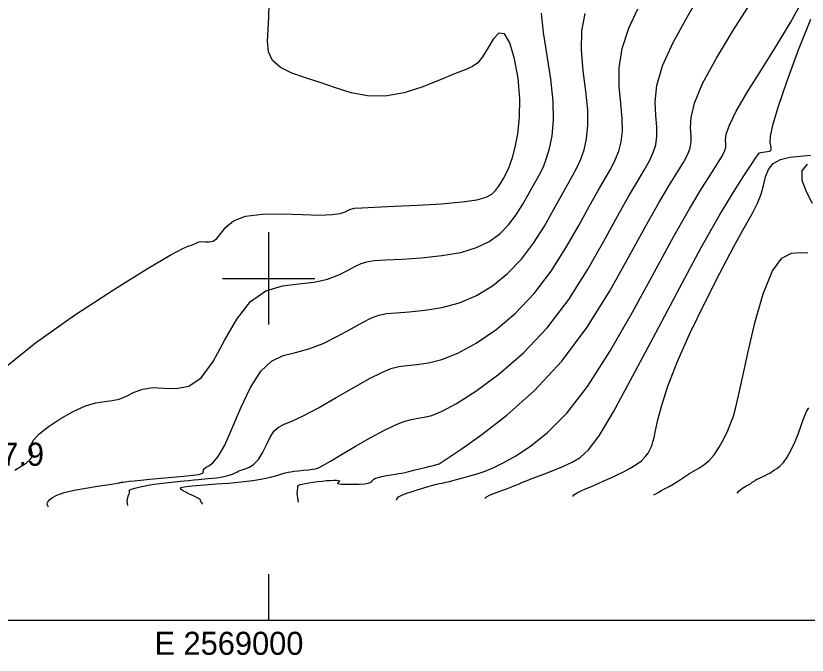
# Model space of a CAD drawing. Extents: x 2566142 to 2571431, y 418755 to 421584.
# Drawn here: x 2568835 to 2569351, y 418755 to 419171 of the extents above; entities that cross this region are included whole.
import ezdxf

# ---------------------------------------------------------------- set-up
doc = ezdxf.new("R2010")
doc.units = 0
for name, color, linetype in [('Contour_ADS_Major', 7, 'Continuous'), ('Contour_ADS_Minor', 7, 'Continuous'), ('Contour_ADS_Spot_Elevation', 7, 'Continuous'), ('Contour_ADS_State_Plane_Border', 7, 'Continuous'), ('Contour_ADS_Tick', 7, 'Continuous')]:
    doc.layers.add(name, color=color, linetype=linetype)

# ---------------------------------------------------------------- blocks, each defined once
blk = doc.blocks.new('S890')
at = {"layer": 'Contour_ADS_Tick'}
for p, q in [((0, -0.5), (0, 0.5)), ((-0.5, 0), (0.5, 0))]:
    blk.add_line(p, q, dxfattribs=at)

msp = doc.modelspace()

# ---------------------------------------------------------------- linework, layer by layer
at = {"layer": 'Contour_ADS_Major'}
for points in [[(2568856.63, 418851.15), (2568856.2, 418851.99), (2568855.76, 418852.87), (2568855.59, 418853.25), (2568855.55, 418853.49), (2568855.64, 418853.76), (2568855.92, 418854.2), (2568856.47, 418854.92), (2568857.4, 418856.02), (2568859.11, 418857.42), (2568862.07, 418858.99), (2568866.75, 418860.6), (2568873.34, 418862.14), (2568880.97, 418863.54), (2568888.49, 418864.74), (2568894.78, 418865.68), (2568898.97, 418866.32), (2568901.36, 418866.72), (2568902.55, 418866.95), (2568903.11, 418867.09), (2568903.56, 418867.2), (2568904.19, 418867.33), (2568905.17, 418867.48), (2568906.73, 418867.67), (2568909.05, 418867.94), (2568912.33, 418868.29), (2568916.78, 418868.72), (2568922.57, 418869.26), (2568929.71, 418869.9), (2568937.42, 418870.59), (2568944.72, 418871.28), (2568950.63, 418871.91), (2568954.44, 418872.45), (2568956.46, 418872.93), (2568957.26, 418873.43), (2568957.41, 418874), (2568957.43, 418874.69), (2568957.59, 418875.46), (2568958.11, 418876.27), (2568959.21, 418877.06), (2568961.06, 418877.97), (2568963.7, 418879.91), (2568967.13, 418884.01), (2568971.34, 418891.37), (2568976.3, 418902.55), (2568981.94, 418915.83), (2568988.14, 418928.95), (2568994.79, 418939.61), (2569001.83, 418946.22), (2569009.32, 418949.73), (2569017.36, 418951.8), (2569026.07, 418954.05), (2569035.42, 418957.71), (2569044.84, 418962.37), (2569053.64, 418967.2), (2569061.12, 418971.37), (2569066.89, 418974.27), (2569071.74, 418976.05), (2569076.79, 418977.08), (2569083.13, 418977.69), (2569091.56, 418978.28), (2569101.68, 418979.26), (2569112.8, 418981.08), (2569124.2, 418984.17), (2569135.29, 418988.9), (2569145.82, 418995.25), (2569155.64, 419003.14), (2569164.61, 419012.48), (2569172.59, 419023.03), (2569179.6, 419034.04), (2569185.62, 419044.63), (2569190.68, 419053.9), (2569194.82, 419061.25), (2569198.2, 419067.15), (2569201, 419072.36), (2569203.4, 419077.64), (2569205.51, 419083.68), (2569207.13, 419090.84), (2569207.99, 419099.41), (2569207.81, 419109.71), (2569206.53, 419121.83), (2569204.84, 419135.05), (2569203.67, 419148.48), (2569203.93, 419161.21), (2569206.14, 419172.49)], [(2569140.86, 418856.83), (2569141.86, 418857.77), (2569144.28, 418859.07), (2569147.13, 418860.21), (2569150.12, 418861.26), (2569152.97, 418862.28), (2569155.56, 418863.26), (2569157.82, 418864.15), (2569159.66, 418864.89), (2569161.04, 418865.45), (2569162.12, 418865.9), (2569163.07, 418866.3), (2569164.08, 418866.73), (2569165.37, 418867.27), (2569167.22, 418868.03), (2569169.95, 418869.11), (2569173.88, 418870.63), (2569179.16, 418872.65), (2569185.32, 418875.06), (2569191.71, 418877.68), (2569197.71, 418880.37), (2569202.97, 418883.33), (2569208.4, 418888.36), (2569215.21, 418897.61), (2569224.6, 418913.26), (2569237.32, 418936.48), (2569252.19, 418964.51), (2569267.56, 418993.61), (2569281.79, 419020.02), (2569293.53, 419040.78), (2569302.71, 419056.04), (2569309.56, 419066.75), (2569314.29, 419073.85), (2569317.21, 419078.24), (2569318.85, 419080.63), (2569319.81, 419081.65), (2569320.68, 419081.98), (2569321.93, 419082.15), (2569323.44, 419082.32), (2569324.95, 419082.55), (2569326.22, 419082.87), (2569327.03, 419083.33), (2569327.4, 419084.03), (2569327.42, 419085.03), (2569327.16, 419086.42), (2569326.79, 419088.49), (2569326.96, 419092.43), (2569328.4, 419099.63), (2569331.85, 419111.48), (2569337.75, 419128.64), (2569345.24, 419148.77), (2569353.19, 419168.77)]]:
    msp.add_lwpolyline(points, dxfattribs=at)
at = {"layer": 'Contour_ADS_Minor'}
for points in [[(2568957.05, 418853.16), (2568956.47, 418853.88), (2568955.83, 418854.8), (2568955.64, 418855.23), (2568955.6, 418855.5), (2568955.61, 418855.71), (2568955.61, 418855.87), (2568955.56, 418856.01), (2568955.4, 418856.15), (2568955.04, 418856.35), (2568954.38, 418856.68), (2568953.32, 418857.2), (2568951.81, 418857.96), (2568949.97, 418858.88), (2568947.99, 418859.89), (2568946.03, 418860.88), (2568944.29, 418861.78), (2568943.03, 418862.58), (2568942.53, 418863.28), (2568943.05, 418863.88), (2568944.84, 418864.4), (2568947.99, 418864.86), (2568952.51, 418865.3), (2568958.47, 418865.74), (2568965.78, 418866.22), (2568973.86, 418866.79), (2568982.04, 418867.5), (2568989.61, 418868.38), (2568996.02, 418869.46), (2569001.25, 418870.64), (2569005.38, 418871.77), (2569008.51, 418872.72), (2569010.8, 418873.39), (2569012.62, 418873.83), (2569014.4, 418874.15), (2569016.58, 418874.44), (2569019.43, 418874.78), (2569022.66, 418875.14), (2569025.83, 418875.48), (2569028.5, 418875.76), (2569030.47, 418876.03), (2569032.44, 418876.68), (2569035.37, 418878.18), (2569040.2, 418881), (2569047.53, 418885.41), (2569056.54, 418890.78), (2569066.06, 418896.29), (2569074.92, 418901.1), (2569082.22, 418904.56), (2569088.11, 418906.81), (2569092.97, 418908.17), (2569097.24, 418908.96), (2569101.39, 418909.6), (2569106.32, 418910.85), (2569112.98, 418913.57), (2569122.35, 418918.61), (2569135.01, 418926.65), (2569149.99, 418937.67), (2569165.93, 418951.45), (2569181.47, 418967.81), (2569195.48, 418986.31), (2569207.75, 419005.62), (2569218.31, 419024.18), (2569227.19, 419040.44), (2569234.43, 419053.24), (2569240.2, 419062.97), (2569244.68, 419070.46), (2569248.07, 419076.5), (2569250.53, 419081.84), (2569252.11, 419087), (2569252.85, 419092.44), (2569252.78, 419098.63), (2569252.1, 419105.99), (2569251.75, 419114.85), (2569252.83, 419125.5), (2569256.44, 419138.25), (2569263.19, 419153.05), (2569271.7, 419168.54), (2569280.09, 419183.01)], [(2568827.81, 418941.71), (2568848.18, 418958.1), (2568873.59, 418975.99), (2568899.5, 418992.96), (2568921.42, 419006.59), (2568935.92, 419015.13), (2568944.04, 419019.47), (2568947.92, 419021.12), (2568949.7, 419021.64), (2568951.15, 419022.26), (2568952.72, 419023.02), (2568954.46, 419023.69), (2568956.45, 419024.01), (2568958.73, 419023.88), (2568961.22, 419023.76), (2568963.77, 419024.26), (2568966.28, 419025.97), (2568968.79, 419029.23), (2568972.1, 419033.37), (2568977.17, 419037.43), (2568984.97, 419040.48), (2568996.02, 419041.85), (2569008.95, 419041.96), (2569021.94, 419041.5), (2569033.19, 419041.17), (2569041.29, 419041.49), (2569046.59, 419042.34), (2569049.86, 419043.43), (2569051.86, 419044.44), (2569053.47, 419045.16), (2569055.95, 419045.65), (2569060.67, 419046.03), (2569069.02, 419046.43), (2569081.72, 419046.96), (2569097.04, 419047.67), (2569112.61, 419048.58), (2569126.05, 419049.73), (2569135.56, 419051.14), (2569141.64, 419052.84), (2569145.35, 419054.83), (2569147.74, 419057.14), (2569149.71, 419059.74), (2569151.44, 419062.46), (2569152.93, 419065.07), (2569154.18, 419067.36), (2569155.22, 419069.26), (2569156.21, 419071.33), (2569157.32, 419074.27), (2569158.73, 419078.79), (2569160.5, 419085.46), (2569162.25, 419094.19), (2569163.49, 419104.76), (2569163.7, 419116.95), (2569162.54, 419130.24), (2569160.23, 419143), (2569157.11, 419153.29), (2569153.55, 419159.21), (2569149.86, 419159.5), (2569146.19, 419155.65), (2569142.65, 419149.82), (2569139.36, 419144.18), (2569136.26, 419140.36), (2569132.72, 419137.9), (2569127.93, 419135.82), (2569121.1, 419133.14), (2569111.7, 419129.2), (2569100.4, 419124.76), (2569088.15, 419120.87), (2569075.9, 419118.62), (2569064.4, 419118.77), (2569053.65, 419120.83), (2569043.43, 419123.98), (2569033.54, 419127.42), (2569023.93, 419130.56), (2569015.11, 419133.66), (2569007.77, 419137.22), (2569002.58, 419141.72), (2568999.96, 419147.49), (2568999.27, 419154.35), (2568999.64, 419161.94), (2569000.19, 419169.92), (2569000.36, 419178.04)], [(2568908.25, 418852.18), (2568907.88, 418854.99), (2568908.16, 418857.32), (2568908.74, 418858.98), (2568909.23, 418860.13), (2568909.34, 418860.93), (2568909.23, 418861.48), (2568909.16, 418861.88), (2568909.4, 418862.23), (2568910.14, 418862.62), (2568911.32, 418863.04), (2568912.8, 418863.49), (2568914.48, 418863.94), (2568916.28, 418864.4), (2568918.49, 418864.88), (2568921.43, 418865.41), (2568925.47, 418866), (2568930.75, 418866.66), (2568936.72, 418867.35), (2568942.62, 418868), (2568947.73, 418868.55), (2568951.48, 418868.94), (2568954.18, 418869.22), (2568956.3, 418869.41), (2568958.33, 418869.56), (2568960.67, 418869.72), (2568963.29, 418869.93), (2568966.08, 418870.23), (2568968.91, 418870.67), (2568971.67, 418871.26), (2568974.21, 418871.95), (2568976.41, 418872.68), (2568978.12, 418873.36), (2568979.3, 418873.95), (2568980.22, 418874.46), (2568981.22, 418874.96), (2568982.65, 418875.47), (2568984.77, 418876.11), (2568987.42, 418877.18), (2568990.34, 418879.05), (2568993.26, 418882.11), (2568995.98, 418886.51), (2568998.55, 418891.63), (2569001.06, 418896.63), (2569003.6, 418900.68), (2569006.38, 418903.25), (2569009.99, 418905.06), (2569015.14, 418907.13), (2569022.52, 418910.49), (2569032.49, 418915.82), (2569043.97, 418922.38), (2569055.53, 418929.08), (2569065.75, 418934.84), (2569073.6, 418938.83), (2569079.64, 418941.26), (2569084.85, 418942.6), (2569090.18, 418943.33), (2569096.48, 418943.94), (2569104, 418945.05), (2569112.89, 418947.32), (2569123.28, 418951.39), (2569135.15, 418957.77), (2569147.9, 418966.46), (2569160.78, 418977.3), (2569173.04, 418990.14), (2569184.04, 419004.67), (2569193.67, 419019.83), (2569201.97, 419034.41), (2569208.94, 419047.17), (2569214.63, 419057.24), (2569219.2, 419065.06), (2569222.84, 419071.41), (2569225.73, 419077.07), (2569228.02, 419082.76), (2569229.62, 419088.92), (2569230.42, 419095.93), (2569230.29, 419104.17), (2569229.31, 419113.91), (2569228.3, 419124.95), (2569228.25, 419136.99), (2569230.18, 419149.73), (2569234.66, 419162.77), (2569240.51, 419175.34)], [(2569019.46, 418854.41), (2569018.88, 418857.14), (2569018.63, 418860.09), (2569018.71, 418862.2), (2569018.9, 418863.63), (2569019.02, 418864.56), (2569019.2, 418865.12), (2569019.63, 418865.48), (2569020.48, 418865.77), (2569021.9, 418866.11), (2569023.84, 418866.5), (2569026.21, 418866.92), (2569028.92, 418867.34), (2569031.86, 418867.74), (2569034.87, 418868.08), (2569037.76, 418868.36), (2569040.36, 418868.55), (2569042.51, 418868.64), (2569044.17, 418868.62), (2569045.35, 418868.52), (2569046.04, 418868.33), (2569046.26, 418868.08), (2569046.12, 418867.78), (2569045.75, 418867.45), (2569045.27, 418867.12), (2569044.87, 418866.81), (2569044.86, 418866.53), (2569045.62, 418866.3), (2569047.51, 418866.14), (2569050.72, 418866.06), (2569054.74, 418866.07), (2569058.85, 418866.18), (2569062.37, 418866.4), (2569064.75, 418866.73), (2569066.15, 418867.15), (2569066.91, 418867.64), (2569067.35, 418868.17), (2569067.79, 418868.73), (2569068.44, 418869.3), (2569069.53, 418869.89), (2569071.27, 418870.48), (2569073.77, 418871.07), (2569076.74, 418871.63), (2569079.79, 418872.15), (2569082.54, 418872.59), (2569084.72, 418872.96), (2569086.63, 418873.31), (2569088.66, 418873.74), (2569091.21, 418874.33), (2569094.56, 418875.13), (2569098.33, 418876.04), (2569102.04, 418876.94), (2569105.17, 418877.71), (2569107.35, 418878.25), (2569108.74, 418878.59), (2569109.59, 418878.82), (2569110.18, 418879), (2569110.95, 418879.33), (2569112.99, 418880.57), (2569117.57, 418883.61), (2569125.94, 418889.33), (2569138.86, 418898.46), (2569155.14, 418911.05), (2569173.07, 418927), (2569190.95, 418946.21), (2569207.36, 418968.26), (2569221.96, 418991.5), (2569234.68, 419013.97), (2569245.44, 419033.71), (2569254.23, 419049.23), (2569261.2, 419060.88), (2569266.52, 419069.5), (2569270.41, 419075.92), (2569273.04, 419080.92), (2569274.6, 419085.08), (2569275.28, 419088.96), (2569275.26, 419093.09), (2569274.89, 419098.07), (2569275.21, 419104.74), (2569277.41, 419114.01), (2569282.7, 419126.76), (2569291.71, 419143.33), (2569302.88, 419161.74), (2569314.08, 419179.44)], [(2569083.36, 418855.68), (2569083.44, 418856.31), (2569084.64, 418857.91), (2569086.66, 418859.01), (2569089.44, 418859.98), (2569092.86, 418861.1), (2569096.63, 418862.33), (2569100.43, 418863.54), (2569103.93, 418864.6), (2569106.88, 418865.41), (2569109.27, 418866), (2569111.2, 418866.42), (2569112.74, 418866.74), (2569114.01, 418867.01), (2569115.3, 418867.31), (2569116.93, 418867.7), (2569119.23, 418868.28), (2569122.44, 418869.09), (2569126.42, 418870.14), (2569130.97, 418871.41), (2569135.85, 418872.89), (2569140.97, 418874.62), (2569146.61, 418876.91), (2569153.18, 418880.11), (2569161.08, 418884.57), (2569170.6, 418890.78), (2569181.67, 418899.67), (2569194.12, 418912.3), (2569207.78, 418929.73), (2569222.34, 418952.37), (2569237.09, 418978.02), (2569251.15, 419003.84), (2569263.69, 419026.98), (2569274.04, 419045.22), (2569282.19, 419058.79), (2569288.36, 419068.55), (2569292.74, 419075.35), (2569295.55, 419080), (2569297.09, 419083.17), (2569297.71, 419085.47), (2569297.74, 419087.54), (2569297.61, 419090.05), (2569298.12, 419093.83), (2569300.16, 419099.78), (2569304.61, 419108.79), (2569311.98, 419121.34), (2569321.25, 419136.23), (2569331.03, 419151.87), (2569339.91, 419166.63), (2569346.8, 419179.2)], [(2568834.7, 418875.17), (2568838.85, 418877.72), (2568842.26, 418880.03), (2568844.43, 418881.87), (2568845.52, 418883.28), (2568845.91, 418884.34), (2568845.96, 418885.14), (2568845.95, 418885.8), (2568845.89, 418886.44), (2568845.75, 418887.22), (2568845.45, 418888.27), (2568845.07, 418889.75), (2568845.25, 418891.84), (2568846.74, 418894.71), (2568850.3, 418898.55), (2568856.36, 418903.39), (2568864.17, 418908.61), (2568872.63, 418913.44), (2568880.66, 418917.1), (2568887.42, 418919.09), (2568893.07, 418919.94), (2568898.01, 418920.45), (2568902.64, 418921.43), (2568907.34, 418923.41), (2568912.37, 418925.87), (2568917.98, 418928.01), (2568924.39, 418929.05), (2568931.76, 418928.64), (2568939.76, 418928.26), (2568948.01, 418929.86), (2568956.09, 418935.36), (2568963.74, 418945.92), (2568971.31, 418959.56), (2568979.29, 418973.49), (2568988.15, 418984.94), (2568998.19, 418991.88), (2569008.92, 418995.21), (2569019.63, 418996.57), (2569029.63, 418997.61), (2569038.36, 418999.6), (2569045.72, 419002.35), (2569051.75, 419005.31), (2569056.49, 419007.91), (2569060.18, 419009.72), (2569063.85, 419010.85), (2569068.73, 419011.55), (2569076.07, 419012.06), (2569086.64, 419012.62), (2569099.36, 419013.46), (2569112.7, 419014.83), (2569125.13, 419016.95), (2569135.43, 419020.02), (2569143.73, 419024.05), (2569150.49, 419028.99), (2569156.17, 419034.81), (2569161.15, 419041.39), (2569165.52, 419048.25), (2569169.27, 419054.85), (2569172.43, 419060.63), (2569175.02, 419065.25), (2569177.21, 419069.24), (2569179.16, 419073.31), (2569181.06, 419078.22), (2569183, 419084.6), (2569184.64, 419092.75), (2569185.56, 419102.9), (2569185.33, 419115.25), (2569183.74, 419129.75), (2569181.39, 419145.15), (2569179.09, 419159.97), (2569177.67, 419172.7)], [(2569198.18, 418857.98), (2569198.88, 418859.11), (2569200.91, 418860.49), (2569203.48, 418861.7), (2569206.29, 418862.94), (2569209.2, 418864.21), (2569212.16, 418865.49), (2569215.09, 418866.75), (2569217.97, 418867.98), (2569220.9, 418869.25), (2569224.04, 418870.66), (2569227.55, 418872.31), (2569231.48, 418874.25), (2569235.58, 418876.44), (2569239.48, 418878.81), (2569242.82, 418881.28), (2569245.35, 418883.77), (2569247.15, 418886.17), (2569248.37, 418888.37), (2569249.2, 418890.25), (2569249.79, 418891.83), (2569250.34, 418893.7), (2569251.01, 418896.55), (2569251.99, 418901.09), (2569253.51, 418907.94), (2569256.03, 418917.45), (2569260.06, 418929.87), (2569266.1, 418945.45), (2569274.39, 418964.07), (2569284.04, 418984.09), (2569293.88, 419003.48), (2569302.75, 419020.23), (2569309.73, 419032.86), (2569314.88, 419042.03), (2569318.5, 419048.94), (2569320.89, 419054.81), (2569322.41, 419060.57), (2569323.73, 419066.1), (2569325.55, 419070.98), (2569328.6, 419074.84), (2569333.36, 419077.39), (2569339.43, 419078.88), (2569346.18, 419079.66), (2569352.98, 419080.1)], [(2569354.22, 419048.68), (2569350.26, 419056.34), (2569347.57, 419063.81), (2569347.54, 419070.05), (2569351.03, 419074.31)], [(2569250.86, 418859.03), (2569251.72, 418859.67), (2569253.64, 418860.75), (2569255.91, 418861.91), (2569258.36, 418863.21), (2569260.93, 418864.65), (2569263.57, 418866.18), (2569266.21, 418867.8), (2569268.82, 418869.46), (2569271.46, 418871.18), (2569274.2, 418872.92), (2569277.11, 418874.69), (2569280.24, 418876.53), (2569283.53, 418878.69), (2569286.88, 418881.48), (2569290.21, 418885.21), (2569293.43, 418890.05), (2569296.4, 418895.54), (2569299.01, 418901.08), (2569301.13, 418906.07), (2569302.72, 418910.31), (2569304.16, 418915.23), (2569305.92, 418922.63), (2569308.45, 418934.34), (2569312.11, 418951.3), (2569316.78, 418970.99), (2569322.21, 418989.99), (2569328.16, 419004.9), (2569334.37, 419013.26), (2569340.52, 419016.46), (2569346.28, 419016.82), (2569351.29, 419016.66)], [(2569305.08, 418860.12), (2569306.46, 418861.72), (2569308.7, 418863.39), (2569310.88, 418864.69), (2569312.66, 418865.75), (2569314.02, 418866.61), (2569315.03, 418867.28), (2569315.76, 418867.77), (2569316.26, 418868.11), (2569316.6, 418868.34), (2569316.86, 418868.5), (2569317.09, 418868.65), (2569317.36, 418868.83), (2569317.65, 418869.02), (2569317.93, 418869.2), (2569318.18, 418869.34), (2569318.39, 418869.44), (2569318.7, 418869.56), (2569319.25, 418869.8), (2569320.2, 418870.22), (2569321.63, 418870.9), (2569323.33, 418871.72), (2569325.02, 418872.56), (2569326.42, 418873.3), (2569327.34, 418873.84), (2569327.99, 418874.27), (2569328.64, 418874.73), (2569329.6, 418875.35), (2569331.09, 418876.28), (2569333.04, 418877.78), (2569335.33, 418880.13), (2569337.83, 418883.61), (2569340.4, 418888.33), (2569342.89, 418893.79), (2569345.12, 418899.29), (2569346.94, 418904.17), (2569348.27, 418907.94), (2569349.33, 418910.84), (2569350.44, 418913.32), (2569351.9, 418915.8)]]:
    msp.add_lwpolyline(points, dxfattribs=at)
at = {"layer": 'Contour_ADS_State_Plane_Border'}
msp.add_line((2569000, 418777.5), (2569000, 418807.5), dxfattribs=at)
msp.add_lwpolyline([(2566164.43, 418777.5), (2571407.81, 418777.5), (2571407.81, 421561.67), (2566164.43, 421561.67), (2566164.43, 418777.5)], close=True, dxfattribs=at)

# ---------------------------------------------------------------- block references
at = {"layer": 'Contour_ADS_Tick', "xscale": 60, "yscale": 60}
msp.add_blockref('S890', (2569000, 419000), dxfattribs=at)

# ---------------------------------------------------------------- texts
at = {"layer": 'Contour_ADS_Spot_Elevation'}
msp.add_text('747.9', height=15, dxfattribs=at).set_placement((2568803.46, 418878.07))
at = {"layer": 'Contour_ADS_State_Plane_Border'}
msp.add_text(' E 2569000', height=15, dxfattribs=at).set_placement((2568920, 418755))

doc.saveas('drawing.dxf')
